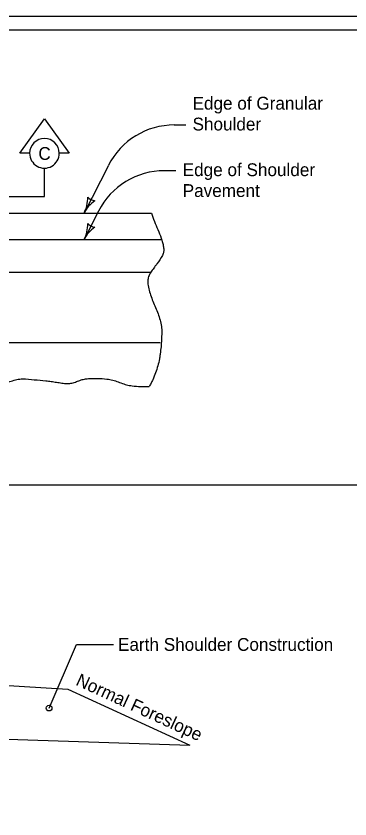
# Model space of a CAD drawing. Extents: x 10038 to 81668, y 7924 to 11018.
# Drawn here: x 11812 to 12229, y 8942 to 9944 of the extents above; entities that cross this region are included whole.
import ezdxf

# ---------------------------------------------------------------- set-up
doc = ezdxf.new("R2010")
doc.units = 0
for name, color, linetype in [('DsnShtMinorGrid06', 7, 'Continuous'), ('DsnShtMinorGrid10', 7, 'Continuous'), ('DsnShtMinorGrid11', 7, 'Continuous'), ('DsnShtMinorGrid13', 7, 'Continuous'), ('DsnShtMinorGrid14', 7, 'Continuous'), ('Level 60', 7, 'Continuous'), ('SheetBorder', 7, 'Continuous')]:
    doc.layers.add(name, color=color, linetype=linetype)

msp = doc.modelspace()

# ---------------------------------------------------------------- linework, layer by layer
at = {"layer": 'DsnShtMinorGrid06'}
msp.add_line((10150.3, 9926.7), (13246, 9926.7), dxfattribs=at)
at = {"layer": 'DsnShtMinorGrid10'}
for p, q in [((12009.9, 9808.1), (12024.2, 9808.1)), ((11927.6, 9757.7), (11897.1, 9698)), ((11997.6, 9751.1), (12011.9, 9751.1)), ((11915.3, 9700.7), (11897.1, 9665)), ((11853.5, 9080.3), (11887.8, 9159.7)), ((11887.8, 9159.7), (11934.1, 9159.7))]:
    msp.add_line(p, q, dxfattribs=at)
for centre, radius, start, end in [((12009.9, 9715.7), 92.4, 90, 152.9341), ((11997.6, 9658.6), 92.4, 90, 152.9341), ((11859.3, 9717.3), 42.5, 332.9341, 1.0066), ((11934.9, 9678.6), 42.5, 124.8616, 152.9341), ((11913.3, 9729.7), 16.4, 225.2008, 260.6675), ((11859.3, 9684.3), 42.5, 332.9341, 1.0066), ((11934.9, 9645.7), 42.5, 124.8616, 152.9341), ((11913.3, 9696.7), 16.4, 225.2008, 260.6675)]:
    msp.add_arc(centre, radius, start, end, dxfattribs=at)
at = {"layer": 'DsnShtMinorGrid11'}
for p, q in [((10350.4, 9536.4), (11992.4, 9536.4)), ((12305.9, 9358.7), (10150.3, 9358.7))]:
    msp.add_line(p, q, dxfattribs=at)
at = {"layer": 'DsnShtMinorGrid13'}
for p, q in [((11847.7, 9718.8), (11847.7, 9754.3)), ((11759.6, 9718.8), (11847.7, 9718.8))]:
    msp.add_line(p, q, dxfattribs=at)
msp.add_lwpolyline([(11829.2, 9772.7), (11816.9, 9772.7), (11847.7, 9815.9), (11878.5, 9772.7), (11866.2, 9772.7)], dxfattribs=at)
for start, end in [(0.0008, 179.9992), (179.9992, 0.0008)]:
    msp.add_arc((11847.7, 9772.7), 18.5, start, end, dxfattribs=at)
at = {"layer": 'DsnShtMinorGrid14'}
msp.add_circle((11853.5, 9080.3), 3.54, dxfattribs=at)
at = {"layer": 'Level 60'}
for p, q in [((11803.6, 9698), (11981.5, 9698)), ((11913.3, 9696.8), (11897.1, 9665)), ((10345.8, 9665), (11993.3, 9665)), ((10367, 9624.3), (11980.8, 9624.3)), ((11742, 9112.3), (11876.8, 9103.9)), ((11876.8, 9103.9), (12029.3, 9033.9)), ((11546, 9049.7), (12029.3, 9033.9))]:
    msp.add_line(p, q, dxfattribs=at)
for points in [[(11981.5, 9698), (11985, 9687.8), (11989.3, 9677.5), (11993.5, 9666.8), (11995.2, 9661.4), (11996.3, 9656), (11996.7, 9650.6), (11996.5, 9649.2), (11996.2, 9647.8), (11995.1, 9645.3), (11988.2, 9634.8), (11986.2, 9632.1), (11984.3, 9629.5), (11982.3, 9626.9), (11980.4, 9624.2), (11977.8, 9618.8), (11976.8, 9613.3), (11977, 9609.5), (11977.6, 9605.6), (11979.6, 9597.9), (11985.6, 9582.2), (11991.6, 9566.5), (11993.5, 9558.6), (11994.2, 9550.8), (11994, 9542.2), (11993.5, 9533.5), (11992.6, 9524.8), (11992, 9520.5), (11991.3, 9516.1), (11989.3, 9507.4), (11986.6, 9498.8), (11983, 9490.1), (11980.8, 9485.8), (11979.6, 9483.7), (11978.4, 9481.5)], [(11698.7, 9485.3), (11700.7, 9485.4), (11708.3, 9485.9), (11715.8, 9486.5), (11723.4, 9487.3), (11730.9, 9488.2), (11735.7, 9489.2), (11740.3, 9490.7), (11745, 9492), (11747.4, 9492.5), (11749.7, 9492.8), (11756.3, 9492.8), (11762.9, 9492.1), (11769.4, 9491.1), (11776, 9489.9), (11780, 9489), (11783.9, 9487.8), (11787.9, 9486.7), (11791.9, 9485.9), (11795.5, 9485.9), (11799, 9486.4), (11806.1, 9488.3), (11813.3, 9490.4), (11820.4, 9491.1), (11835, 9490.1), (11849.5, 9488.8), (11856.2, 9488), (11862.9, 9487), (11869.6, 9486), (11876.3, 9485.4), (11882.1, 9485.9), (11887.7, 9487.8), (11893.4, 9489.8), (11899.1, 9491.1), (11906.6, 9491.6), (11914.2, 9491.7), (11925.6, 9491), (11929.4, 9490.5), (11936.4, 9488.7), (11943.3, 9486.1), (11950.2, 9483.8), (11957.3, 9482.5), (11978.4, 9481.5)]]:
    msp.add_spline(points, degree=3, dxfattribs=at)
at = {"layer": 'SheetBorder'}
msp.add_lwpolyline([(10132.5, 9944), (13267.5, 9944), (13267.5, 7924), (10132.5, 7924)], close=True, dxfattribs=at)

# ---------------------------------------------------------------- texts
at = {"layer": 'DsnShtMinorGrid10'}
for s, p in [('Edge of Granular', (12032.7, 9827.2)), ('Shoulder', (12032.7, 9801.2)), ('Edge of Shoulder', (12020.4, 9744.2)), ('Pavement', (12020.4, 9718.2)), ('Earth Shoulder Construction', (11939.6, 9151.7))]:
    msp.add_text(s, height=16, dxfattribs=at).set_placement(p)
msp.add_text('Normal Foreslope', height=16, rotation=335.372, dxfattribs=at).set_placement((11885.7, 9109.5))
at = {"layer": 'DsnShtMinorGrid13'}
msp.add_text('C', height=16, dxfattribs=at).set_placement((11840.1, 9764.5))

doc.saveas('drawing.dxf')
